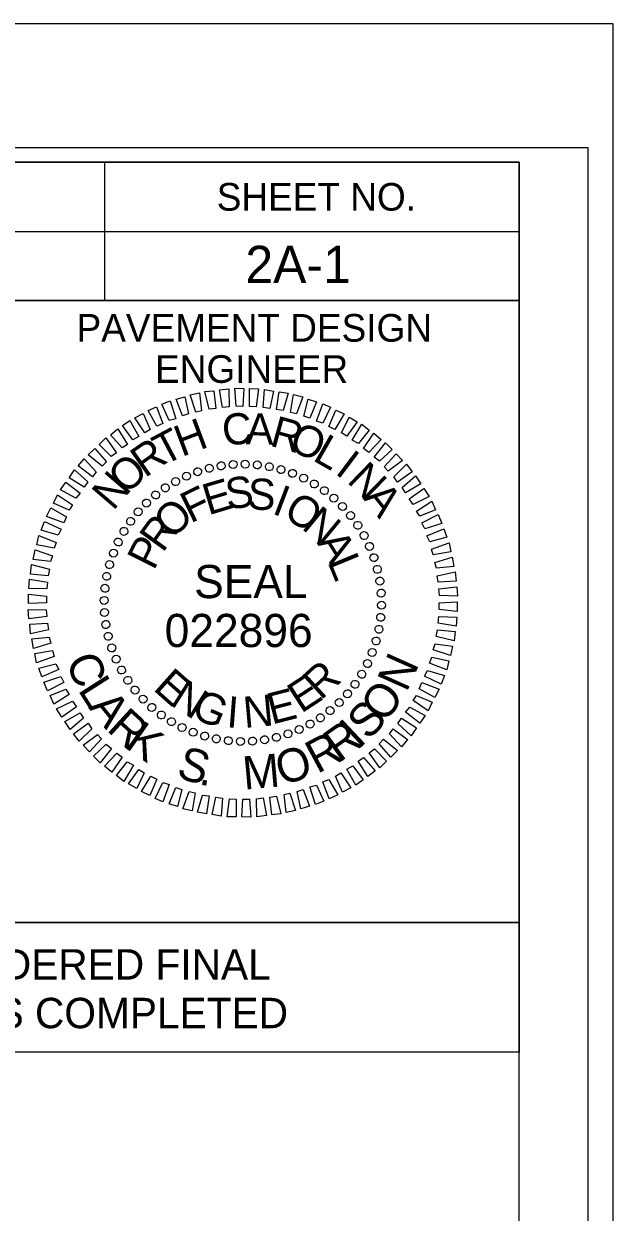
# Model space of a CAD drawing. Extents: x 55823 to 57507, y 47399 to 48499.
# Drawn here: x 57400.6 to 57507.2, y 48284.4 to 48499.4 of the extents above; entities that cross this region are included whole.
import ezdxf

# ---------------------------------------------------------------- set-up
doc = ezdxf.new("R2010")
doc.units = 0
for name, color, linetype in [('Sheet Data Field CELL', 7, 'Continuous'), ('Sheet PE Seal Cell', 7, 'Continuous'), ('Sheet Plot Border Inside CELL', 7, 'Continuous'), ('Sheet Plot Border Outside CELL', 7, 'Continuous'), ('Sheet Sticker Exception Certification CELL', 7, 'Continuous'), ('Sheet Typical CELL', 7, 'Continuous')]:
    doc.layers.add(name, color=color, linetype=linetype)

msp = doc.modelspace()

# ---------------------------------------------------------------- linework, layer by layer
at = {"layer": 'Sheet PE Seal Cell'}
for p, q in [((57440.63, 48419.75), (57440.63, 48419.75)), ((57429.98, 48417.6), (57429.98, 48417.6)), ((57431.98, 48418.4), (57431.98, 48418.4)), ((57434.08, 48419), (57434.08, 48419)), ((57436.28, 48419.4), (57436.28, 48419.4)), ((57438.43, 48419.7), (57438.43, 48419.7)), ((57442.83, 48419.6), (57442.83, 48419.6)), ((57444.98, 48419.25), (57444.98, 48419.25)), ((57447.08, 48418.8), (57447.08, 48418.8)), ((57449.18, 48418.1), (57449.18, 48418.1)), ((57426.13, 48415.45), (57426.13, 48415.45)), ((57428.03, 48416.6), (57428.03, 48416.6)), ((57451.18, 48417.2), (57451.18, 48417.2)), ((57453.13, 48416.2), (57453.13, 48416.2)), ((57424.38, 48414.2), (57424.38, 48414.2)), ((57454.93, 48414.95), (57454.93, 48414.95)), ((57456.68, 48413.6), (57456.68, 48413.6)), ((57421.23, 48411.15), (57421.23, 48411.15)), ((57422.73, 48412.7), (57422.73, 48412.7)), ((57458.23, 48412.1), (57458.23, 48412.1)), ((57419.88, 48409.4), (57419.88, 48409.4)), ((57459.73, 48410.45), (57459.73, 48410.45)), ((57418.63, 48407.6), (57418.63, 48407.6)), ((57460.98, 48408.7), (57460.98, 48408.7)), ((57417.63, 48405.65), (57417.63, 48405.65)), ((57462.13, 48406.8), (57462.13, 48406.8)), ((57463.13, 48404.85), (57463.13, 48404.85)), ((57416.73, 48403.65), (57416.73, 48403.65)), ((57463.93, 48402.85), (57463.93, 48402.85)), ((57416.03, 48401.55), (57416.03, 48401.55)), ((57464.53, 48400.75), (57464.53, 48400.75)), ((57415.58, 48399.45), (57415.58, 48399.45)), ((57464.93, 48398.55), (57464.93, 48398.55)), ((57415.23, 48397.3), (57415.23, 48397.3)), ((57465.23, 48396.4), (57465.23, 48396.4)), ((57415.08, 48395.1), (57415.08, 48395.1)), ((57440.18, 48394.65), (57440.18, 48394.65)), ((57465.28, 48394.2), (57465.28, 48394.2)), ((57415.13, 48392.9), (57415.13, 48392.9)), ((57465.13, 48392), (57465.13, 48392)), ((57415.43, 48390.75), (57415.43, 48390.75)), ((57464.78, 48389.85), (57464.78, 48389.85)), ((57415.83, 48388.55), (57415.83, 48388.55)), ((57464.33, 48387.75), (57464.33, 48387.75)), ((57416.43, 48386.45), (57416.43, 48386.45)), ((57463.63, 48385.65), (57463.63, 48385.65)), ((57417.23, 48384.45), (57417.23, 48384.45)), ((57462.73, 48383.65), (57462.73, 48383.65)), ((57418.23, 48382.5), (57418.23, 48382.5)), ((57461.73, 48381.7), (57461.73, 48381.7)), ((57419.38, 48380.6), (57419.38, 48380.6)), ((57460.48, 48379.9), (57460.48, 48379.9)), ((57420.63, 48378.85), (57420.63, 48378.85)), ((57422.13, 48377.2), (57422.13, 48377.2)), ((57459.13, 48378.15), (57459.13, 48378.15)), ((57423.68, 48375.7), (57423.68, 48375.7)), ((57455.98, 48375.1), (57455.98, 48375.1)), ((57457.63, 48376.6), (57457.63, 48376.6)), ((57425.43, 48374.35), (57425.43, 48374.35)), ((57427.23, 48373.1), (57427.23, 48373.1)), ((57452.33, 48372.7), (57452.33, 48372.7)), ((57454.23, 48373.85), (57454.23, 48373.85)), ((57429.18, 48372.1), (57429.18, 48372.1)), ((57431.18, 48371.2), (57431.18, 48371.2)), ((57433.28, 48370.5), (57433.28, 48370.5)), ((57446.28, 48370.3), (57446.28, 48370.3)), ((57448.38, 48370.9), (57448.38, 48370.9)), ((57450.38, 48371.7), (57450.38, 48371.7)), ((57435.38, 48370.05), (57435.38, 48370.05)), ((57437.53, 48369.7), (57437.53, 48369.7)), ((57439.73, 48369.55), (57439.73, 48369.55)), ((57441.93, 48369.6), (57441.93, 48369.6)), ((57444.08, 48369.9), (57444.08, 48369.9))]:
    msp.add_line(p, q, dxfattribs=at)
for points in [[(57434.08, 48429.65), (57433.28, 48432.85), (57434.93, 48433), (57435.28, 48429.8)], [(57436.48, 48429.95), (57435.93, 48433.15), (57437.63, 48433.35), (57437.68, 48430.1)], [(57438.98, 48430.2), (57438.73, 48433.45), (57440.38, 48433.4), (57440.18, 48430.15)], [(57441.38, 48430.15), (57441.38, 48433.4), (57443.03, 48433.35), (57442.58, 48430.1)], [(57443.88, 48430), (57444.08, 48433.25), (57445.73, 48432.95), (57445.08, 48429.8)], [(57446.28, 48429.6), (57446.73, 48432.8), (57448.38, 48432.55), (57447.48, 48429.45)], [(57426.83, 48427.65), (57425.53, 48430.55), (57427.03, 48431.15), (57428.08, 48427.95)], [(57429.28, 48428.45), (57428.13, 48431.45), (57429.68, 48431.9), (57430.33, 48428.8)], [(57431.68, 48429.1), (57430.63, 48432.25), (57432.33, 48432.6), (57432.73, 48429.35)], [(57448.83, 48429.05), (57449.33, 48432.3), (57451.03, 48431.9), (57449.88, 48428.8)], [(57451.23, 48428.4), (57451.98, 48431.5), (57453.53, 48431), (57452.28, 48428.05)], [(57453.48, 48427.5), (57454.63, 48430.65), (57456.03, 48430.05), (57454.63, 48427.15)], [(57422.48, 48425.4), (57420.63, 48428.1), (57422.18, 48428.9), (57423.43, 48426)], [(57424.63, 48426.6), (57423.03, 48429.4), (57424.58, 48430.1), (57425.73, 48427.05)], [(57455.73, 48426.55), (57456.98, 48429.5), (57458.53, 48428.8), (57456.83, 48426)], [(57420.28, 48424.15), (57418.43, 48426.7), (57419.73, 48427.65), (57421.38, 48424.75)], [(57458.03, 48425.4), (57459.38, 48428.25), (57460.88, 48427.4), (57458.98, 48424.8)], [(57459.98, 48424.05), (57461.73, 48426.95), (57463.03, 48425.9), (57461.08, 48423.45)], [(57416.38, 48421.1), (57414.18, 48423.3), (57415.38, 48424.5), (57417.33, 48421.8)], [(57418.38, 48422.65), (57416.23, 48425.05), (57417.58, 48426.1), (57419.33, 48423.3)], [(57462.03, 48422.55), (57463.88, 48425.3), (57465.18, 48424.2), (57462.98, 48421.85)], [(57414.73, 48419.35), (57412.18, 48421.4), (57413.43, 48422.55), (57415.53, 48420.15)], [(57463.93, 48421), (57465.98, 48423.6), (57467.18, 48422.4), (57464.88, 48420.25)], [(57412.98, 48417.45), (57410.38, 48419.4), (57411.48, 48420.7), (57413.68, 48418.35)], [(57465.73, 48419.25), (57467.88, 48421.6), (57469.08, 48420.4), (57466.48, 48418.45)], [(57411.48, 48415.55), (57408.78, 48417.25), (57409.73, 48418.7), (57412.13, 48416.5)], [(57467.48, 48417.45), (57469.78, 48419.7), (57470.83, 48418.35), (57468.18, 48416.45)], [(57468.98, 48415.5), (57471.43, 48417.6), (57472.38, 48416.15), (57469.58, 48414.55)], [(57409.98, 48413.55), (57407.18, 48415.05), (57408.18, 48416.45), (57410.78, 48414.45)], [(57408.78, 48411.4), (57405.93, 48412.65), (57406.68, 48414.2), (57409.38, 48412.35)], [(57470.28, 48413.45), (57472.93, 48415.35), (57473.88, 48413.85), (57470.98, 48412.45)], [(57407.78, 48409.1), (57404.68, 48410.25), (57405.43, 48411.8), (57408.28, 48410.2)], [(57471.58, 48411.25), (57474.38, 48413), (57475.03, 48411.45), (57472.18, 48410.3)], [(57406.78, 48406.9), (57403.68, 48407.8), (57404.33, 48409.35), (57407.33, 48407.95)], [(57472.58, 48409.1), (57475.53, 48410.6), (57476.18, 48409), (57473.08, 48408)], [(57473.48, 48406.75), (57476.53, 48408.05), (57477.08, 48406.5), (57473.98, 48405.7)], [(57406.03, 48404.5), (57402.93, 48405.15), (57403.28, 48406.8), (57406.43, 48405.55)], [(57474.28, 48404.35), (57477.48, 48405.5), (57477.78, 48403.85), (57474.63, 48403.3)], [(57405.38, 48402.1), (57402.28, 48402.5), (57402.63, 48404.2), (57405.78, 48403.15)], [(57474.88, 48401.95), (57478.03, 48402.9), (57478.33, 48401.2), (57475.18, 48400.9)], [(57404.98, 48399.55), (57401.78, 48399.85), (57401.98, 48401.55), (57405.23, 48400.75)], [(57404.73, 48397.15), (57401.48, 48397.25), (57401.58, 48398.9), (57404.83, 48398.35)], [(57475.33, 48399.55), (57478.58, 48400.25), (57478.73, 48398.55), (57475.53, 48398.35)], [(57404.68, 48394.65), (57401.43, 48394.5), (57401.43, 48396.2), (57404.68, 48395.85)], [(57475.63, 48397.15), (57478.88, 48397.55), (57478.98, 48395.85), (57475.73, 48395.95)], [(57475.68, 48394.65), (57478.93, 48394.8), (57478.93, 48393.1), (57475.68, 48393.45)], [(57404.73, 48392.15), (57401.48, 48391.75), (57401.38, 48393.45), (57404.63, 48393.35)], [(57475.63, 48392.15), (57478.88, 48392.05), (57478.78, 48390.4), (57475.53, 48390.95)], [(57405.03, 48389.75), (57401.78, 48389.05), (57401.63, 48390.75), (57404.83, 48390.95)], [(57475.38, 48389.75), (57478.58, 48389.45), (57478.38, 48387.75), (57475.13, 48388.55)], [(57405.48, 48387.35), (57402.33, 48386.4), (57402.03, 48388.1), (57405.18, 48388.4)], [(57406.08, 48384.95), (57402.88, 48383.8), (57402.58, 48385.45), (57405.73, 48386)], [(57474.98, 48387.2), (57478.08, 48386.8), (57477.73, 48385.1), (57474.58, 48386.15)], [(57406.88, 48382.55), (57403.83, 48381.25), (57403.28, 48382.8), (57406.38, 48383.6)], [(57474.33, 48384.8), (57477.43, 48384.15), (57477.08, 48382.5), (57473.93, 48383.75)], [(57407.78, 48380.2), (57404.83, 48378.7), (57404.18, 48380.3), (57407.28, 48381.3)], [(57473.58, 48382.4), (57476.68, 48381.5), (57476.03, 48379.95), (57473.03, 48381.35)], [(57408.78, 48378.05), (57405.98, 48376.3), (57405.33, 48377.85), (57408.18, 48379)], [(57472.58, 48380.2), (57475.68, 48379.05), (57474.93, 48377.5), (57472.08, 48379.1)], [(57410.08, 48375.85), (57407.43, 48373.95), (57406.48, 48375.45), (57409.38, 48376.85)], [(57471.58, 48377.9), (57474.43, 48376.65), (57473.68, 48375.1), (57470.98, 48376.95)], [(57411.38, 48373.8), (57408.93, 48371.7), (57407.98, 48373.15), (57410.78, 48374.75)], [(57470.38, 48375.75), (57473.18, 48374.25), (57472.18, 48372.85), (57469.58, 48374.85)], [(57412.88, 48371.85), (57410.58, 48369.6), (57409.53, 48370.95), (57412.18, 48372.85)], [(57468.88, 48373.75), (57471.58, 48372.05), (57470.63, 48370.6), (57468.23, 48372.8)], [(57414.63, 48370.05), (57412.48, 48367.7), (57411.28, 48368.9), (57413.88, 48370.85)], [(57467.38, 48371.85), (57469.98, 48369.9), (57468.88, 48368.6), (57466.68, 48370.95)], [(57416.43, 48368.3), (57414.38, 48365.7), (57413.18, 48366.9), (57415.48, 48369.05)], [(57463.98, 48368.2), (57466.18, 48366), (57464.98, 48364.8), (57463.03, 48367.5)], [(57465.63, 48369.95), (57468.18, 48367.9), (57466.93, 48366.75), (57464.83, 48369.15)], [(57418.33, 48366.75), (57416.48, 48364), (57415.18, 48365.1), (57417.38, 48367.45)], [(57461.98, 48366.65), (57464.13, 48364.25), (57462.78, 48363.2), (57461.03, 48366)], [(57420.38, 48365.25), (57418.63, 48362.35), (57417.33, 48363.4), (57419.28, 48365.85)], [(57422.33, 48363.9), (57420.98, 48361.05), (57419.48, 48361.9), (57421.38, 48364.5)], [(57457.88, 48363.9), (57459.73, 48361.2), (57458.18, 48360.4), (57456.93, 48363.3)], [(57460.08, 48365.15), (57461.93, 48362.6), (57460.63, 48361.65), (57458.98, 48364.55)], [(57424.63, 48362.75), (57423.38, 48359.8), (57421.83, 48360.5), (57423.53, 48363.3)], [(57426.88, 48361.8), (57425.73, 48358.65), (57424.33, 48359.25), (57425.73, 48362.15)], [(57455.73, 48362.7), (57457.33, 48359.9), (57455.78, 48359.2), (57454.63, 48362.25)], [(57429.13, 48360.9), (57428.38, 48357.8), (57426.83, 48358.3), (57428.08, 48361.25)], [(57431.53, 48360.25), (57431.03, 48357), (57429.33, 48357.4), (57430.48, 48360.5)], [(57434.08, 48359.7), (57433.63, 48356.5), (57431.98, 48356.75), (57432.88, 48359.85)], [(57446.28, 48359.65), (57447.08, 48356.45), (57445.43, 48356.3), (57445.08, 48359.5)], [(57448.68, 48360.2), (57449.73, 48357.05), (57448.03, 48356.7), (57447.63, 48359.95)], [(57451.08, 48360.85), (57452.23, 48357.85), (57450.68, 48357.4), (57450.03, 48360.5)], [(57453.53, 48361.65), (57454.83, 48358.75), (57453.33, 48358.15), (57452.28, 48361.35)], [(57436.48, 48359.3), (57436.28, 48356.05), (57434.63, 48356.35), (57435.28, 48359.5)], [(57438.98, 48359.15), (57438.98, 48355.9), (57437.33, 48355.95), (57437.78, 48359.2)], [(57441.38, 48359.1), (57441.63, 48355.85), (57439.98, 48355.9), (57440.18, 48359.15)], [(57443.88, 48359.35), (57444.43, 48356.15), (57442.73, 48355.95), (57442.68, 48359.2)]]:
    msp.add_lwpolyline(points, close=True, dxfattribs=at)
for centre, major_axis in [((57434.11, 48418.98), (-0.174, 0.699)), ((57436.26, 48419.42), (-0.113, 0.711)), ((57438.43, 48419.66), (-0.05, 0.718)), ((57440.62, 48419.72), (0.013, 0.72)), ((57442.8, 48419.59), (0.075, 0.716)), ((57444.97, 48419.26), (0.137, 0.707)), ((57429.98, 48417.56), (-0.293, 0.658)), ((57432.01, 48418.36), (-0.234, 0.681)), ((57447.09, 48418.75), (0.198, 0.692)), ((57449.17, 48418.06), (0.258, 0.672)), ((57451.17, 48417.19), (0.316, 0.647)), ((57426.16, 48415.44), (-0.403, 0.597)), ((57428.02, 48416.58), (-0.349, 0.63)), ((57453.1, 48416.14), (0.371, 0.617)), ((57454.92, 48414.94), (0.423, 0.582)), ((57422.76, 48412.69), (-0.5, 0.518)), ((57424.4, 48414.14), (-0.453, 0.56)), ((57456.63, 48413.57), (0.472, 0.543)), ((57421.25, 48411.1), (-0.543, 0.472)), ((57458.22, 48412.07), (0.518, 0.5)), ((57459.67, 48410.43), (0.56, 0.453)), ((57419.89, 48409.39), (-0.582, 0.423)), ((57460.97, 48408.67), (0.597, 0.403)), ((57418.68, 48407.56), (-0.617, 0.371)), ((57462.12, 48406.8), (0.63, 0.349)), ((57417.64, 48405.64), (-0.647, 0.316)), ((57463.09, 48404.85), (0.658, 0.293)), ((57416.77, 48403.63), (-0.672, 0.258)), ((57463.89, 48402.81), (0.681, 0.234)), ((57416.07, 48401.56), (-0.692, 0.198)), ((57464.51, 48400.71), (0.699, 0.174)), ((57415.56, 48399.43), (-0.707, 0.137)), ((57464.95, 48398.57), (0.711, 0.113)), ((57415.24, 48397.27), (-0.716, 0.075)), ((57465.2, 48396.4), (0.718, 0.05)), ((57415.1, 48395.08), (-0.72, 0.013)), ((57465.26, 48394.21), (0.72, -0.013)), ((57415.16, 48392.9), (-0.718, -0.05)), ((57465.12, 48392.02), (0.716, -0.075)), ((57415.41, 48390.72), (-0.711, -0.113)), ((57464.8, 48389.86), (0.707, -0.137)), ((57415.84, 48388.58), (-0.699, -0.174)), ((57464.29, 48387.73), (0.692, -0.198)), ((57416.47, 48386.48), (-0.681, -0.234)), ((57463.59, 48385.66), (0.672, -0.258)), ((57417.27, 48384.44), (-0.658, -0.293)), ((57418.24, 48382.49), (-0.63, -0.349)), ((57462.72, 48383.65), (0.647, -0.316)), ((57419.39, 48380.62), (-0.597, -0.403)), ((57461.68, 48381.73), (0.617, -0.371)), ((57420.69, 48378.86), (-0.56, -0.453)), ((57459.11, 48378.19), (0.543, -0.472)), ((57460.47, 48379.9), (0.582, -0.423)), ((57422.14, 48377.22), (-0.518, -0.5)), ((57457.6, 48376.6), (0.5, -0.518)), ((57423.73, 48375.72), (-0.472, -0.543)), ((57425.44, 48374.36), (-0.423, -0.582)), ((57454.2, 48373.85), (0.403, -0.597)), ((57455.96, 48375.15), (0.453, -0.56)), ((57427.26, 48373.15), (-0.371, -0.617)), ((57429.19, 48372.1), (-0.316, -0.647)), ((57450.38, 48371.73), (0.293, -0.658)), ((57452.34, 48372.71), (0.349, -0.63)), ((57431.19, 48371.23), (-0.258, -0.672)), ((57433.27, 48370.54), (-0.198, -0.692)), ((57435.39, 48370.03), (-0.137, -0.707)), ((57437.56, 48369.7), (-0.075, -0.716)), ((57439.74, 48369.57), (-0.013, -0.72)), ((57441.93, 48369.63), (0.05, -0.718)), ((57444.1, 48369.87), (0.113, -0.711)), ((57446.25, 48370.31), (0.174, -0.699)), ((57448.35, 48370.93), (0.234, -0.681))]:
    msp.add_ellipse(centre, major_axis=major_axis, ratio=0.999708, dxfattribs=at)
at = {"layer": 'Sheet Plot Border Inside CELL'}
msp.add_lwpolyline([(57502.66, 48476.93), (55836.16, 48476.93), (55836.16, 47421.83), (57502.66, 47421.83)], close=True, dxfattribs=at)
at = {"layer": 'Sheet Plot Border Outside CELL'}
msp.add_lwpolyline([(57507.16, 48499.38), (55823.16, 48499.38), (55823.16, 47399.38), (57507.16, 47399.38)], close=True, dxfattribs=at)
at = {"layer": 'Sheet Sticker Exception Certification CELL'}
for p, q in [((57290.13, 48336.83), (57490.16, 48336.83)), ((57490.16, 48336.82), (57490.16, 48313.32)), ((57490.16, 48313.33), (57290.13, 48313.33))]:
    msp.add_line(p, q, dxfattribs=at)
at = {"layer": 'Sheet Typical CELL'}
for p, q in [((57415.16, 48474.33), (57415.16, 48449.33)), ((57290.11, 48461.83), (57490.16, 48461.83))]:
    msp.add_line(p, q, dxfattribs=at)
for points in [[(57490.16, 48474.38), (55990.16, 48474.38), (55990.16, 47424.38), (57490.16, 47424.38)], [(57290.11, 48474.38), (57490.16, 48474.38), (57490.16, 48449.33), (57290.11, 48449.33)], [(57390.16, 48449.33), (57490.16, 48449.33), (57490.16, 48336.83), (57390.16, 48336.83)]]:
    msp.add_lwpolyline(points, close=True, dxfattribs=at)

# ---------------------------------------------------------------- texts
at = {"layer": 'Sheet Data Field CELL'}
msp.add_text('2A-1', height=6.75, dxfattribs=at).set_placement((57440.64, 48452.48))
at = {"layer": 'Sheet PE Seal Cell'}
for s, height, rotation, p in [('C', 5.64, 6.2199, (57436.73, 48423)), ('A', 5.64, 359.0203, (57440.68, 48423.3)), ('R', 5.64, 344.6211, (57444.88, 48423.1)), ('T', 5.64, 27.8198, (57425.88, 48419.35)), ('H', 5.64, 20.6195, (57429.13, 48421)), ('O', 5.64, 337.4212, (57448.23, 48422.35)), ('L', 5.64, 330.2209, (57452.63, 48420.5)), ('R', 5.64, 35.0205, (57422.48, 48417.15)), ('I', 5.64, 323.0201, (57456.68, 48418.1)), ('O', 5.64, 42.2217, (57419.03, 48414.05)), ('N', 5.64, 315.8189, (57458.83, 48416.55)), ('N', 5.64, 49.4235, (57416.73, 48411.15)), ('S', 5.64, 7.2556, (57437.38, 48411.5)), ('F', 5.64, 25.967, (57430.73, 48408.95)), ('E', 5.64, 16.6111, (57433.93, 48410.45)), ('S', 5.64, 357.9004, (57440.98, 48411.55)), ('I', 5.64, 339.1896, (57445.28, 48410.85)), ('A', 5.64, 308.6172, (57461.78, 48413.6)), ('O', 5.64, 329.8335, (57447.28, 48410.15)), ('O', 5.64, 44.6812, (57427.43, 48406)), ('N', 5.64, 320.4766, (57450.63, 48408.15)), ('R', 5.64, 54.0397, (57425.68, 48403.55)), ('P', 5.64, 63.3989, (57424.08, 48400.35)), ('A', 5.64, 301.7603, (57453.48, 48405.55)), ('L', 5.64, 292.4008, (57455.43, 48402.1)), ('SEAL', 5.998, 360, (57431.38, 48395.49)), ('C', 6, 292.9481, (57408.05, 48384.1)), ('N', 6, 65.9082, (57469.79, 48378.32)), ('R', 5.64, 42.4814, (57454.28, 48376.9)), ('L', 6, 302.5303, (57410.25, 48378.9)), ('E', 5.64, 318.2769, (57423.78, 48379)), ('E', 5.64, 33.1241, (57450.73, 48374.55)), ('N', 5.64, 327.634, (57426.78, 48376.3)), ('E', 5.64, 14.4118, (57445.43, 48372.6)), ('O', 6, 54.3478, (57465.92, 48372.71)), ('A', 6, 308.805, (57412.15, 48375.72)), ('G', 5.64, 336.9902, (57430.58, 48374.05)), ('I', 5.64, 355.7012, (57437.13, 48372.15)), ('N', 5.64, 5.0564, (57440.48, 48372)), ('R', 6, 317.6453, (57415.39, 48371.64)), ('S', 6, 47.0221, (57462.91, 48369.61)), ('K', 6, 325.1256, (57418.6, 48368.61)), ('R', 6, 35.7399, (57457.58, 48365.65)), ('I', 6, 43.2201, (57461.2, 48368.16)), ('R', 6, 28.2596, (57453.65, 48363.63)), ('S', 6, 343.6099, (57427.97, 48363.11)), ('O', 6, 16.6992, (57447.16, 48361.56)), ('M', 6, 5.1697, (57440.41, 48360.83)), ('.', 6, 350.9356, (57432.09, 48361.81))]:
    msp.add_text(s, height=height, rotation=rotation, dxfattribs=at).set_placement(p)
msp.add_text('022896', height=5.998, dxfattribs=at).set_placement((57426.04, 48386.64))
at = {"layer": 'Sheet Sticker Exception Certification CELL'}
for s, p in [('DOCUMENT NOT CONSIDERED FINAL', (57311.2, 48326.49)), ('UNLESS ALL SIGNATURES COMPLETED', (57306.13, 48317.69))]:
    msp.add_text(s, height=5.5, dxfattribs=at).set_placement(p)
at = {"layer": 'Sheet Typical CELL'}
for s, height, p in [('SHEET NO.', 5, (57435.46, 48465.58)), ('PAVEMENT DESIGN', 5.0001, (57410.11, 48441.88)), ('ENGINEER', 5, (57424.31, 48434.43))]:
    msp.add_text(s, height=height, dxfattribs=at).set_placement(p)

doc.saveas('drawing.dxf')
